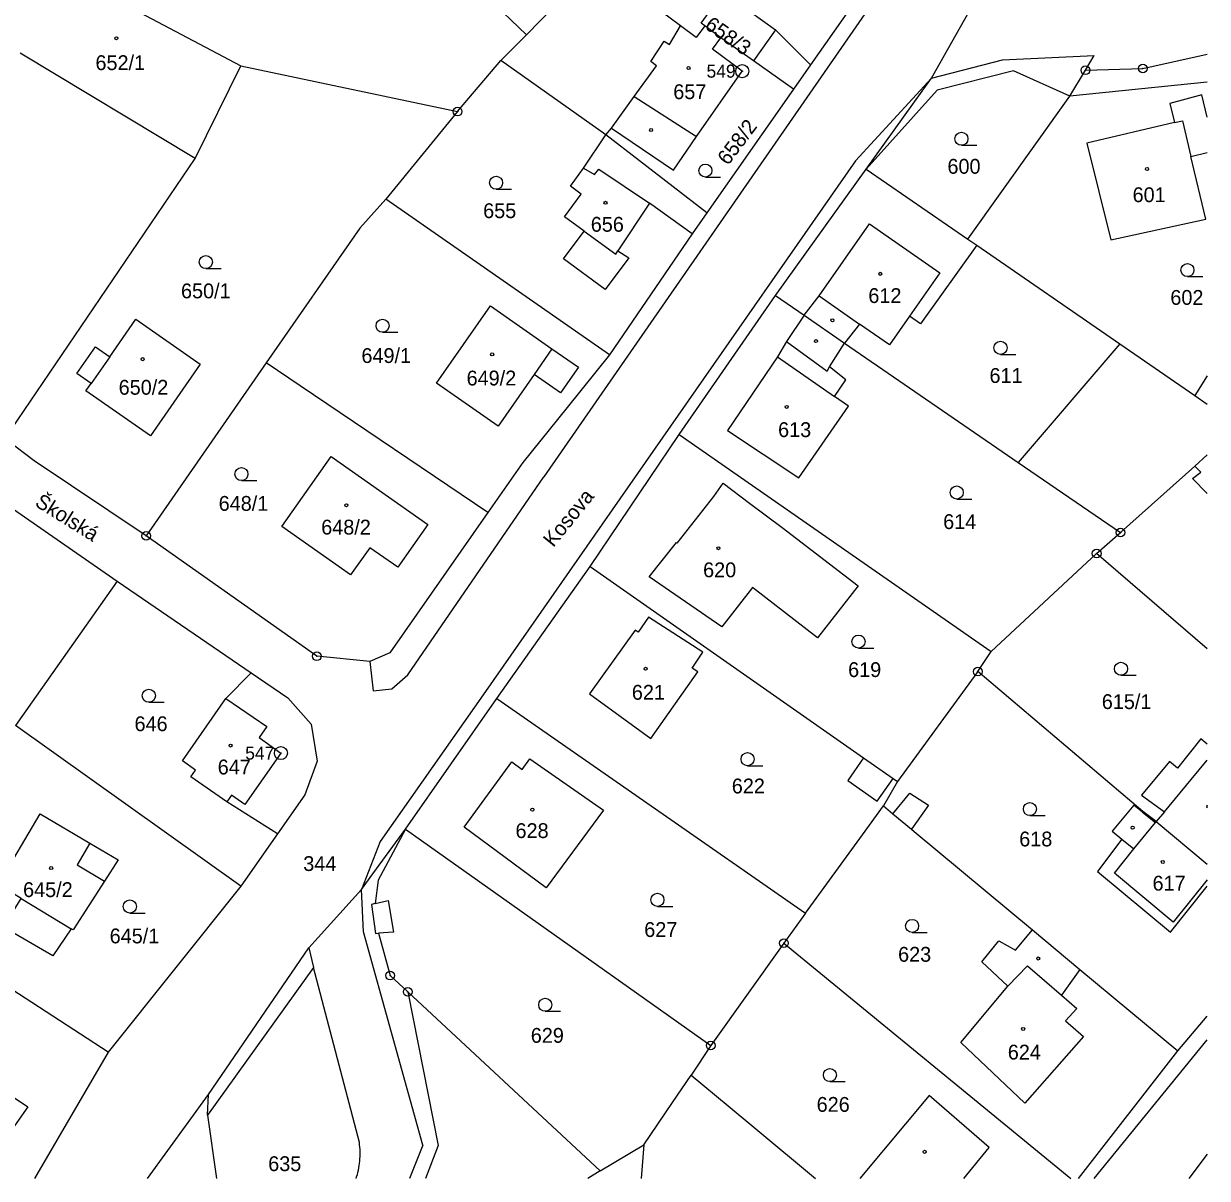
# Model space of a CAD drawing. Extents: x -749778 to -749372, y -967291 to -966955.
# Drawn here: x -749507.7 to -749371.9, y -967290.9 to -967158.5 of the extents above; entities that cross this region are included whole.
import ezdxf

# ---------------------------------------------------------------- set-up
doc = ezdxf.new("R2010")
doc.units = 0
for name, color, linetype in [('Hranice parcel', 7, 'Continuous'), ('Parcelní čísla', 7, 'Continuous'), ('Pop  PČ popisy', 7, 'Continuous'), ('Vnitřní kresba', 7, 'Continuous'), ('Značky bodu BP', 7, 'Continuous'), ('Značky budov', 7, 'Continuous'), ('Značky kultur', 7, 'Continuous')]:
    doc.layers.add(name, color=color, linetype=linetype)

msp = doc.modelspace()

# ---------------------------------------------------------------- linework, layer by layer
at = {"layer": 'Hranice parcel'}
for p, q in [((-749450, -967159.75), (-749468.12, -967142.24)), ((-749405.12, -967145.63), (-749417.43, -967163.18)), ((-749495.7, -967156.44), (-749482.75, -967163.3)), ((-749427.72, -967160.08), (-749429.57, -967158.72)), ((-749452.95, -967162.7), (-749450, -967159.75)), ((-749457.9, -967168.55), (-749452.95, -967162.7)), ((-749440.9, -967171.2), (-749452.95, -967162.7)), ((-749482.75, -967163.3), (-749457.9, -967168.55)), ((-749417.43, -967163.18), (-749419.39, -967165.98)), ((-749371.93, -967165.16), (-749387.68, -967166.78)), ((-749419.39, -967165.98), (-749429.33, -967180.15)), ((-749399.38, -967183.18), (-749387.68, -967166.78)), ((-749457.9, -967168.55), (-749466.13, -967178.61)), ((-749429.33, -967180.15), (-749440.9, -967171.2)), ((-749421.46, -967189.65), (-749411.05, -967175.15)), ((-749411.05, -967175.15), (-749399.38, -967183.18)), ((-749429.33, -967180.15), (-749430.99, -967182.56)), ((-749430.99, -967182.56), (-749440.49, -967196.44)), ((-749399.38, -967183.18), (-749398.36, -967183.89)), ((-749432.48, -967205.6), (-749421.46, -967189.65)), ((-749421.46, -967189.65), (-749418.17, -967191.91)), ((-749418.17, -967191.91), (-749413.52, -967195.11)), ((-749479.85, -967197.38), (-749493.61, -967217.22)), ((-749442.71, -967220.75), (-749432.48, -967205.6)), ((-749432.48, -967205.6), (-749396.73, -967230.5)), ((-749384.62, -967219.24), (-749381.88, -967216.84)), ((-749396.73, -967230.5), (-749384.62, -967219.24)), ((-749453.4, -967235.87), (-749442.71, -967220.75)), ((-749496.94, -967222.41), (-749508.59, -967238.99)), ((-749496.94, -967222.41), (-749481.57, -967232.94)), ((-749398.25, -967232.8), (-749396.73, -967230.5)), ((-749398.25, -967232.8), (-749407.46, -967245.39)), ((-749379.31, -967248.84), (-749398.25, -967232.8)), ((-749463.88, -967250.86), (-749453.4, -967235.87)), ((-749453.4, -967235.87), (-749418.02, -967260.49)), ((-749482.77, -967257.42), (-749508.59, -967238.99)), ((-749407.46, -967245.39), (-749409.06, -967248.2)), ((-749377.79, -967250), (-749379.31, -967248.84)), ((-749463.88, -967250.86), (-749428.88, -967275.7)), ((-749478.55, -967251.41), (-749482.77, -967257.42)), ((-749482.77, -967257.42), (-749497.96, -967276.47)), ((-749497.96, -967276.47), (-749523.47, -967259.85)), ((-749418.02, -967260.49), (-749420.48, -967263.96)), ((-749391.98, -967262.43), (-749386.54, -967266.96)), ((-749420.48, -967263.96), (-749428.88, -967275.7)), ((-749420.48, -967263.96), (-749387.57, -967290.93)), ((-749386.54, -967266.96), (-749375.31, -967276.32)), ((-749463.62, -967269.54), (-749441.54, -967290.07)), ((-749375.31, -967276.32), (-749371.93, -967272.33)), ((-749428.88, -967275.7), (-749431.13, -967279.08)), ((-749386.69, -967290.93), (-749375.31, -967276.32)), ((-749441.54, -967290.07), (-749436.56, -967287.09)), ((-749371.93, -967288.16), (-749374.06, -967290.93)), ((-749441.54, -967290.07), (-749442.97, -967290.93))]:
    msp.add_line(p, q, dxfattribs=at)
for points in [[(-749411.05, -967175.15), (-749403.55, -967164.72), (-749394.09, -967147.88), (-749392.2, -967144.33)], [(-749441.95, -967151.55), (-749443.59, -967153.11), (-749450, -967159.75)], [(-749429.57, -967158.72), (-749430.54, -967160.04), (-749432.33, -967158.73), (-749441.95, -967151.55)], [(-749429.57, -967158.72), (-749429.99, -967158.42), (-749427.43, -967154.86), (-749421.43, -967159.17), (-749417.43, -967163.18)], [(-749440.9, -967171.2), (-749440.27, -967170.47), (-749433.15, -967175.26), (-749430.51, -967171.41), (-749425.26, -967163.91), (-749428.69, -967161.4), (-749427.72, -967160.08)], [(-749419.39, -967165.98), (-749423.96, -967162.74), (-749427.72, -967160.08)], [(-749387.68, -967166.78), (-749385.91, -967163.81), (-749379.33, -967163.6), (-749371.93, -967161.97)], [(-749509.79, -967206.06), (-749488, -967173.92), (-749482.75, -967163.3)], [(-749387.68, -967166.78), (-749394.17, -967163.89), (-749402.9, -967166.08), (-749411.05, -967175.15)], [(-749371.93, -967169.2), (-749372.56, -967166.64), (-749376.23, -967167.62), (-749375.68, -967169.81), (-749385.74, -967172.19), (-749383, -967183.25), (-749372.12, -967180.88)], [(-749430.99, -967182.56), (-749435.88, -967179.04), (-749439.53, -967184.54), (-749438.28, -967185.31), (-749440.97, -967188.97), (-749445.74, -967185.44), (-749443.38, -967182.28), (-749445.64, -967180.64), (-749443.73, -967178.01), (-749444.97, -967177.12), (-749443.48, -967175.03), (-749440.9, -967171.2)], [(-749372.12, -967180.88), (-749373.82, -967173.7), (-749371.93, -967173.25)], [(-749466.13, -967178.61), (-749469.13, -967181.93), (-749479.85, -967197.38)], [(-749440.49, -967196.44), (-749462.25, -967181.31), (-749466.13, -967178.61)], [(-749398.36, -967183.89), (-749404.84, -967192.88), (-749406.08, -967192.02), (-749408.39, -967195.32), (-749411.82, -967192.92), (-749413.52, -967195.11)], [(-749398.36, -967183.89), (-749381.96, -967195.19), (-749373.35, -967201.13), (-749371.93, -967202.11)], [(-749453.24, -967204.62), (-749460.31, -967199.71), (-749454.14, -967190.85), (-749447.08, -967195.76), (-749444.04, -967197.87), (-749446.1, -967200.82), (-749449.13, -967198.71), (-749453.24, -967204.62)], [(-749501.56, -967198.61), (-749499.42, -967195.54), (-749497.8, -967196.67), (-749494.81, -967192.38), (-749487.41, -967197.52), (-749493.13, -967205.74), (-749500.53, -967200.58), (-749499.94, -967199.74), (-749501.56, -967198.61)], [(-749418.17, -967191.91), (-749420.2, -967194.93), (-749421.22, -967196.68), (-749426.96, -967205.12), (-749418.79, -967210.56), (-749413.06, -967202.36), (-749414.7, -967201.22), (-749413.38, -967199.31), (-749415.25, -967197.84), (-749413.52, -967195.11)], [(-749413.52, -967195.11), (-749393.61, -967208.79), (-749381.88, -967216.84)], [(-749440.49, -967196.44), (-749445.34, -967202.48), (-749450.42, -967208.8), (-749454.43, -967214.53)], [(-749544.44, -967197.63), (-749542.05, -967198.77), (-749532.66, -967202.89), (-749519.24, -967208.54), (-749514.5, -967210.26), (-749496.94, -967222.41)], [(-749454.43, -967214.53), (-749475.95, -967200.01), (-749479.85, -967197.38)], [(-749493.61, -967217.22), (-749506.47, -967208.63), (-749509.47, -967206.32), (-749509.79, -967206.06)], [(-749478.06, -967216.14), (-749472.42, -967208.12), (-749461.3, -967215.92), (-749464.76, -967220.8), (-749467.98, -967218.58), (-749470.17, -967221.69), (-749478.06, -967216.14)], [(-749381.88, -967216.84), (-749373.38, -967209.24), (-749371.93, -967207.94)], [(-749432.81, -967218), (-749432.71, -967218.06), (-749428.53, -967212.7), (-749427.45, -967211.18), (-749424.42, -967213.46), (-749420.69, -967216.27), (-749411.97, -967222.94), (-749416.62, -967228.93), (-749424.09, -967223.13), (-749427.6, -967227.66), (-749435.93, -967221.91), (-749432.81, -967218)], [(-749454.43, -967214.53), (-749465.69, -967230.63), (-749467.97, -967231.63), (-749474.04, -967231.04), (-749493.61, -967217.22)], [(-749371.93, -967230.18), (-749384.62, -967219.24)], [(-749442.71, -967220.75), (-749411.34, -967242.68), (-749407.95, -967245.05), (-749407.46, -967245.39)], [(-749429.77, -967230.57), (-749436.01, -967226.55), (-749437.18, -967228.28), (-749437.54, -967228.04), (-749442.78, -967235.35), (-749435.74, -967240.46), (-749430.37, -967232.83), (-749431, -967232.41), (-749429.77, -967230.57)], [(-749478.55, -967251.41), (-749484.37, -967247.75), (-749488.49, -967244.88), (-749487.95, -967244.1), (-749489.46, -967243.04), (-749484.48, -967235.9), (-749481.57, -967232.94)], [(-749481.57, -967232.94), (-749477.38, -967235.81), (-749474.71, -967238.83), (-749474.01, -967243.06), (-749475.42, -967246.95), (-749478.55, -967251.41)], [(-749371.93, -967241.13), (-749372.69, -967240.52), (-749375.36, -967243.87), (-749376.28, -967243.11), (-749379.48, -967246.97), (-749376.86, -967248.88), (-749377.79, -967250)], [(-749451.7, -967243.16), (-749450.48, -967244.01), (-749449.63, -967242.79), (-749441.16, -967248.69), (-749447.73, -967257.62), (-749457.16, -967250.63), (-749451.7, -967243.16)], [(-749418.02, -967260.49), (-749411.49, -967251.53), (-749409.06, -967248.2)], [(-749409.06, -967248.2), (-749407.99, -967249.1), (-749405.84, -967250.89), (-749405.53, -967251.14), (-749391.98, -967262.43)], [(-749379.31, -967248.84), (-749379.36, -967248.91), (-749380.35, -967248.1), (-749382.83, -967251.12), (-749381.72, -967252.02), (-749384.52, -967255.73), (-749376.17, -967262.67), (-749371.93, -967257.41)], [(-749502.2, -967262.31), (-749504.3, -967265.4), (-749509.97, -967262.12), (-749507.96, -967258.81), (-749510.57, -967257.23), (-749505.77, -967249.11), (-749500.07, -967252.48), (-749496.82, -967254.4), (-749498.4, -967256.85), (-749501.99, -967262.43), (-749502.2, -967262.31)], [(-749493.48, -967290.93), (-749486.45, -967281.3), (-749474.96, -967264.47), (-749468.93, -967257.79), (-749467.63, -967256.01), (-749463.88, -967250.86)], [(-749463.88, -967250.86), (-749467, -967256.72), (-749467.34, -967259.4), (-749465.85, -967259.06), (-749465.25, -967262.67), (-749466.97, -967262.8), (-749465.63, -967267.67), (-749463.62, -967269.54)], [(-749377.79, -967250), (-749371.93, -967254.9)], [(-749386.54, -967266.96), (-749388.66, -967269.92), (-749386.9, -967271.45), (-749388.21, -967272.87), (-749386.13, -967274.66), (-749392.86, -967282.29), (-749400.19, -967275.35), (-749394.8, -967268.9), (-749397.78, -967266.09), (-749395.85, -967263.67), (-749393.92, -967264.76), (-749391.98, -967262.43)], [(-749463.62, -967269.54), (-749460.13, -967287.18), (-749461.58, -967290.93)], [(-749522, -967290.93), (-749522.55, -967290.57), (-749522.33, -967290.24), (-749523.97, -967289.18), (-749521.64, -967285.6), (-749522.14, -967285.27), (-749518.83, -967280.09), (-749518.29, -967280.44), (-749515.96, -967276.86), (-749507.18, -967282.74), (-749510.88, -967287.97), (-749513.74, -967286.03)], [(-749497.96, -967276.47), (-749506.41, -967290.93)], [(-749436.56, -967287.09), (-749433.26, -967282.23), (-749431.13, -967279.08)], [(-749431.13, -967279.08), (-749426.87, -967282.62), (-749423.69, -967285.26), (-749416.85, -967290.93)], [(-749396.93, -967287.39), (-749403.83, -967281.42), (-749411.77, -967290.93)], [(-749436.56, -967287.09), (-749436.85, -967290.93)], [(-749399.85, -967290.93), (-749396.93, -967287.39)]]:
    msp.add_lwpolyline(points, dxfattribs=at)
at = {"layer": 'Vnitřní kresba'}
for p, q in [((-749403.8, -967146.61), (-749448, -967210.47)), ((-749433.6, -967160.84), (-749432.33, -967158.73)), ((-749421.43, -967159.17), (-749423.96, -967162.74)), ((-749435.73, -967162.82), (-749434.22, -967160.47)), ((-749434.22, -967160.47), (-749433.6, -967160.84)), ((-749488, -967173.92), (-749508.05, -967161.85)), ((-749435.09, -967163.29), (-749435.73, -967162.82)), ((-749403.55, -967164.72), (-749395.41, -967162.63)), ((-749395.41, -967162.63), (-749384.89, -967162.11)), ((-749385.91, -967163.81), (-749384.89, -967162.11)), ((-749437.64, -967166.82), (-749435.09, -967163.29)), ((-749412.26, -967174.2), (-749403.55, -967164.72)), ((-749440.27, -967170.47), (-749437.64, -967166.82)), ((-749437.64, -967166.82), (-749430.51, -967171.41)), ((-749375.68, -967169.81), (-749374.79, -967169.6)), ((-749374.79, -967169.6), (-749373.82, -967173.7)), ((-749412.26, -967174.2), (-749454.7, -967235.06)), ((-749443.48, -967175.03), (-749442.19, -967175.77)), ((-749442.19, -967175.77), (-749441.7, -967175.15)), ((-749441.7, -967175.15), (-749435.88, -967179.04)), ((-749416.45, -967189.68), (-749410.67, -967181.42)), ((-749410.67, -967181.42), (-749402.6, -967187.03)), ((-749443.38, -967182.28), (-749439.77, -967184.9)), ((-749439.77, -967184.9), (-749439.53, -967184.54)), ((-749402.6, -967187.03), (-749406.08, -967192.02)), ((-749418.17, -967191.91), (-749416.45, -967189.68)), ((-749416.45, -967189.68), (-749411.82, -967192.92)), ((-749420.2, -967194.93), (-749415.54, -967198.31)), ((-749381.96, -967195.19), (-749393.61, -967208.79)), ((-749497.8, -967196.67), (-749499.94, -967199.74)), ((-749447.08, -967195.76), (-749449.13, -967198.71)), ((-749421.22, -967196.68), (-749414.7, -967201.22)), ((-749415.54, -967198.31), (-749415.25, -967197.84)), ((-749371.93, -967198.88), (-749373.35, -967201.13)), ((-749463.62, -967233.15), (-749448, -967210.47)), ((-749373.62, -967210.65), (-749372.67, -967209.9)), ((-749372.67, -967209.9), (-749373.38, -967209.24)), ((-749371.93, -967212.38), (-749373.62, -967210.65)), ((-749467.97, -967231.63), (-749467.59, -967235)), ((-749465.43, -967234.77), (-749463.62, -967233.15)), ((-749467.59, -967235), (-749465.43, -967234.77)), ((-749484.48, -967235.9), (-749479.78, -967239.1)), ((-749454.7, -967235.06), (-749466.78, -967252.3)), ((-749479.78, -967239.1), (-749480.67, -967240.37)), ((-749480.67, -967240.37), (-749478.16, -967242.14)), ((-749478.16, -967242.14), (-749482.31, -967248.03)), ((-749411.34, -967242.68), (-749413.17, -967245.29)), ((-749373.78, -967245.18), (-749371.93, -967242.95)), ((-749413.17, -967245.29), (-749409.78, -967247.66)), ((-749409.78, -967247.66), (-749407.95, -967245.05)), ((-749376.86, -967248.88), (-749373.78, -967245.18)), ((-749483.83, -967246.97), (-749484.37, -967247.75)), ((-749482.31, -967248.03), (-749483.83, -967246.97)), ((-749407.99, -967249.1), (-749406.03, -967246.74)), ((-749406.03, -967246.74), (-749403.92, -967248.1)), ((-749403.92, -967248.1), (-749405.84, -967250.89)), ((-749379.36, -967248.91), (-749377.88, -967250.11)), ((-749380.34, -967253.14), (-749377.88, -967250.11)), ((-749377.88, -967250.11), (-749377.79, -967250)), ((-749500.07, -967252.48), (-749501.53, -967254.96)), ((-749466.78, -967252.3), (-749468.93, -967257.79)), ((-749381.72, -967252.02), (-749380.34, -967253.14)), ((-749382.59, -967255.91), (-749380.34, -967253.14)), ((-749501.53, -967254.96), (-749498.4, -967256.85)), ((-749375.83, -967261.55), (-749382.59, -967255.91)), ((-749371.93, -967256.69), (-749375.83, -967261.55)), ((-749468.71, -967262.65), (-749468.93, -967257.79)), ((-749507.96, -967258.81), (-749502.2, -967262.31)), ((-749461.89, -967287.12), (-749468.71, -967262.65)), ((-749474.96, -967264.47), (-749474.43, -967266.76)), ((-749474.43, -967266.76), (-749486.59, -967283.67)), ((-749469.17, -967286.83), (-749474.43, -967266.76)), ((-749394.8, -967268.9), (-749392.54, -967266.54)), ((-749392.54, -967266.54), (-749388.66, -967269.92)), ((-749384.92, -967290.93), (-749371.93, -967275.03)), ((-749486.59, -967283.67), (-749486.45, -967281.3)), ((-749486.59, -967283.67), (-749485.54, -967290.93)), ((-749461.89, -967287.12), (-749463.42, -967290.93))]:
    msp.add_line(p, q, dxfattribs=at)
for points in [[(-749467.34, -967259.4), (-749467.79, -967259.53), (-749467.32, -967262.83), (-749466.97, -967262.8)], [(-749469.53, -967290.93), (-749469.48, -967290.76), (-749469.4, -967290.5), (-749469.34, -967290.25), (-749469.28, -967289.99), (-749469.23, -967289.73), (-749469.18, -967289.47), (-749469.15, -967289.21), (-749469.12, -967288.94), (-749469.1, -967288.68), (-749469.08, -967288.41), (-749469.08, -967288.15), (-749469.08, -967287.88), (-749469.09, -967287.62), (-749469.11, -967287.36), (-749469.14, -967287.09), (-749469.17, -967286.83)]]:
    msp.add_lwpolyline(points, dxfattribs=at)
at = {"layer": 'Značky bodu BP'}
for centre, radius in [((-749425.26, -967163.91), 0.75), ((-749425.26, -967163.91), 0.03), ((-749385.91, -967163.81), 0.5), ((-749385.91, -967163.81), 0.0303), ((-749379.33, -967163.6), 0.5), ((-749379.33, -967163.6), 0.0303), ((-749457.9, -967168.55), 0.5), ((-749457.9, -967168.55), 0.0303), ((-749493.61, -967217.22), 0.5), ((-749493.61, -967217.22), 0.0303), ((-749381.88, -967216.84), 0.5), ((-749381.88, -967216.84), 0.0303), ((-749384.62, -967219.24), 0.5), ((-749384.62, -967219.24), 0.0303), ((-749474.04, -967231.04), 0.5), ((-749474.04, -967231.04), 0.0303), ((-749398.25, -967232.8), 0.5), ((-749398.25, -967232.8), 0.0303), ((-749478.16, -967242.14), 0.75), ((-749478.16, -967242.14), 0.03), ((-749420.48, -967263.96), 0.5), ((-749420.48, -967263.96), 0.0303), ((-749465.63, -967267.67), 0.5), ((-749465.63, -967267.67), 0.0303), ((-749463.62, -967269.54), 0.5), ((-749463.62, -967269.54), 0.0303), ((-749428.88, -967275.7), 0.5), ((-749428.88, -967275.7), 0.0303)]:
    msp.add_circle(centre, radius, dxfattribs=at)
at = {"layer": 'Značky budov'}
msp.add_line((-749371.93, -967248.42), (-749371.93, -967248.12), dxfattribs=at)
for centre in [(-749497.03, -967160.13), (-749431.42, -967163.55), (-749435.71, -967170.67), (-749378.84, -967175.14), (-749440.94, -967179.01), (-749409.44, -967187.16), (-749414.92, -967192.49), (-749416.81, -967194.88), (-749494.01, -967196.95), (-749453.94, -967196.4), (-749420.16, -967202.43), (-749470.66, -967213.71), (-749427.99, -967218.64), (-749436.34, -967232.47), (-749483.94, -967241.28), (-749449.33, -967248.63), (-749380.5, -967250.7), (-749504.51, -967255.33), (-749377.04, -967254.63), (-749391.32, -967265.71), (-749393.05, -967273.79), (-749404.35, -967287.89)]:
    msp.add_circle(centre, 0.175, dxfattribs=at)
msp.add_arc((-749371.85, -967248.27), 0.175, 118.3873, 241.6127, dxfattribs=at)
at = {"layer": 'Značky kultur'}
for p, q in [((-749400.13, -967172.42), (-749398.38, -967172.42)), ((-749429.49, -967176.07), (-749427.74, -967176.07)), ((-749453.49, -967177.46), (-749451.74, -967177.46)), ((-749486.77, -967186.56), (-749485.02, -967186.56)), ((-749374.21, -967187.48), (-749372.46, -967187.48)), ((-749466.51, -967193.87), (-749464.76, -967193.87)), ((-749395.65, -967196.4), (-749393.9, -967196.4)), ((-749482.69, -967210.89), (-749480.94, -967210.89)), ((-749400.67, -967213), (-749398.92, -967213)), ((-749411.93, -967230.1), (-749410.18, -967230.1)), ((-749381.83, -967233.22), (-749380.08, -967233.22)), ((-749493.31, -967236.32), (-749491.56, -967236.32)), ((-749424.65, -967243.59), (-749422.9, -967243.59)), ((-749392.27, -967249.32), (-749390.52, -967249.32)), ((-749495.49, -967260.49), (-749493.74, -967260.49)), ((-749434.99, -967259.73), (-749433.24, -967259.73)), ((-749405.79, -967262.72), (-749404.04, -967262.72)), ((-749447.85, -967271.77), (-749446.1, -967271.77)), ((-749415.21, -967279.83), (-749413.46, -967279.83))]:
    msp.add_line(p, q, dxfattribs=at)
for centre in [(-749400.13, -967171.67), (-749429.49, -967175.32), (-749453.49, -967176.71), (-749486.77, -967185.81), (-749374.21, -967186.73), (-749466.51, -967193.12), (-749395.65, -967195.65), (-749482.69, -967210.14), (-749400.67, -967212.25), (-749411.93, -967229.35), (-749381.83, -967232.47), (-749493.31, -967235.57), (-749424.65, -967242.84), (-749392.27, -967248.57), (-749495.49, -967259.74), (-749434.99, -967258.98), (-749405.79, -967261.97), (-749447.85, -967271.02), (-749415.21, -967279.08)]:
    msp.add_circle(centre, 0.75, dxfattribs=at)

# ---------------------------------------------------------------- texts
at = {"layer": 'Parcelní čísla'}
for s, rotation, p in [('658/3', 325, (-749429.68, -967158.92)), ('658/2', 53, (-749426.89, -967174.81))]:
    msp.add_text(s, height=1.7, rotation=rotation, dxfattribs=at).set_placement(p)
for s, p in [('652/1', (-749499.43, -967163.79)), ('657', (-749433.17, -967167.12)), ('600', (-749401.73, -967175.68)), ('601', (-749380.5, -967178.94)), ('655', (-749454.97, -967180.77)), ('656', (-749442.63, -967182.33)), ('650/1', (-749489.62, -967189.97)), ('612', (-749410.8, -967190.51)), ('602', (-749376.17, -967190.72)), ('649/1', (-749468.93, -967197.39)), ('649/2', (-749456.87, -967199.97)), ('611', (-749396.91, -967199.68)), ('650/2', (-749496.77, -967201.03)), ('613', (-749421.15, -967205.89)), ('648/1', (-749485.3, -967214.35)), ('648/2', (-749473.54, -967217.07)), ('614', (-749402.22, -967216.44)), ('620', (-749429.75, -967221.97)), ('619', (-749413.12, -967233.42)), ('621', (-749437.92, -967236.02)), ('615/1', (-749384.03, -967237.09)), ('646', (-749494.95, -967239.63)), ('647', (-749485.41, -967244.59)), ('622', (-749426.46, -967246.77)), ('628', (-749451.26, -967251.89)), ('618', (-749393.5, -967252.85)), ('344', (-749475.6, -967255.67)), ('617', (-749378.21, -967257.92)), ('645/2', (-749507.73, -967258.66)), ('627', (-749436.5, -967263.24)), ('645/1', (-749497.8, -967263.97)), ('623', (-749407.39, -967266.08)), ('629', (-749449.51, -967275.38)), ('624', (-749394.81, -967277.3)), ('626', (-749416.73, -967283.3)), ('635', (-749479.62, -967290.1))]:
    msp.add_text(s, height=1.7, dxfattribs=at).set_placement(p)
at = {"layer": 'Pop  PČ popisy'}
for s, rotation, p in [('Školská', 328, (-749506.49, -967213.72)), ('Kosova', 51, (-749446.92, -967218.62))]:
    msp.add_text(s, height=1.7, rotation=rotation, dxfattribs=at).set_placement(p)
at = {"layer": 'Značky bodu BP'}
for s, p in [('549', (-749429.36, -967164.66)), ('547', (-749482.26, -967242.89))]:
    msp.add_text(s, height=1.5, dxfattribs=at).set_placement(p)

doc.saveas('drawing.dxf')
